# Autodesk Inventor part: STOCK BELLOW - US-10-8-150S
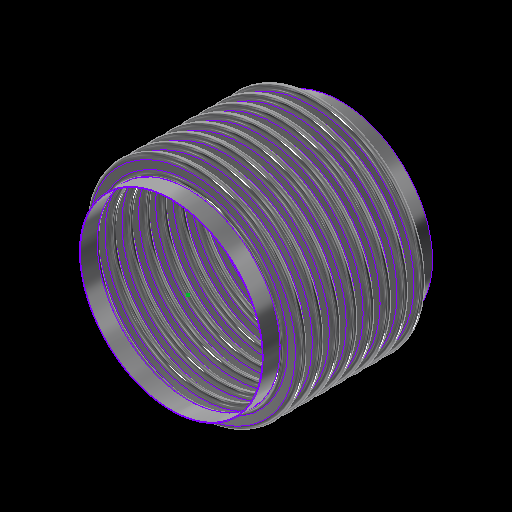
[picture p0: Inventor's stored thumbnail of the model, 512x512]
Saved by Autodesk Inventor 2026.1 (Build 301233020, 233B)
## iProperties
Category: 18 GA (0.048 THICK)
RuleStatus: InUse
Created: 2024-01
Part Number: STOCK BELLOW - US-10-8-150S
Project: =STOCK BELLOWS: <Stock Number><SFILL>
Material: ASTM A240-304
Description: =STOCK BELLOWS: <Stock Number>, <SID_> I.D., <SOD_> O.D., <SPLY_> PLY, <Category>, <SNET_CONS> CONS.<PITCH_><STANGENT_> TANGENT<SFILL>
Document SubType Name: Sheet Metal
Designer: GS
Stock Number: U.S-10-8-150S
Surface Area: 10368.5 cm^2
Volume: 628.223 cm^3
Sheet Metal Rule: Default
Appearance: STAINLESS STEEL
Mass: 5061.77 g
Density: 8.05729 g/cm^3
THK: 0.036
ID: 3.500
OD: 4.250
CONS_: 2
PITCH: 0.500
TANGENT: 0.500
BELLOWS_UPSET: 0.000
d79: 1.000
d82: 1.000
d83: 26.000
d84: 24.000
d174: 8
d214: 8
STHK_: 0.048
SID_: 10.750
SOD_: 12.750
SPITCH_: 1.000
STANGENT__: 1.000
SBELLOWS_UPSET_: 0.000
SDIFF_TAN: 1.000
d252: 2
d275: 2
d287: 0.050
d289: 0.500
d290: 0.000
SOD_NECK: 10 7/8
PLY: 1
PSET: 4.178
PBAR: 1.035
COUNTER: 1.500
NET_TUBE: 3.071
CONS: 2
S_CONS: 0
NET_CONS: 2
ID_M: 88.90 mm
OD_M: 107.95 mm
THK_M: 0.91 mm
ID_U: 3.500 in
OD_U: 4.250 in
THK_U: 0.036 in
TANGENT2: 0.500
TAN_TO_TAN: 1.000 in
d80: 2.571
d81: 10
SID: 2.375
SCONS_: 8
SPITCH: 0.250
STANGENT_: 1.000
SBELLOWS_UPSET: 0.000
SNET_CONS: 8
SS_CONS: 0
SCONS: 8
d190: 8
d191: 1
d192: 1
d193: 8
d194: 0
SIZE: 10.00
PRESSURE: 150
d230: 8
STANGENT: 4.000
SPLY_: 1
d233: 8
d234: 0
d263: 2
d265: 1
d268: 2
d269: 0
d286: 2
d288: 1
d291: 2
d292: 0
SREROLL: 0.750
BLETP: 0.000 ul
PRES_Copy: 85
MATTABLE: 20 GA (0.036 THICK)
PART_NUMBER: U.S-10-8-150S
PITCH_: =, <SPITCH_> PITCH,
CFILL: .
SFILL: .
MESH: ,
COMP: 1.48
EXT: 0.74
LAT: 0.33
ANG: 573
ASR: 2985
LSR: 8692
ANSR: 809
PRES: 150
COMPM: 14.8
EXTM: 7.4
LATM: 3.30
ASRM: 522.763
PRESM: 10.342
LSRM: 1522.230
ANSRM: 141.68
TEMPMIN: 20
TEMPMAX: 800
TEMPMINM: -7
TEMPMAXM: 427
WEIGHTM: 5.062
WEIGHT: 11.159
Author: GS
Keywords: 20 GA (0.036 THICK)
Comments: =STOCK BELLOW - <STOCK NUMBER>
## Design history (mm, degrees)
sketch "Sketch2"
  geometry: L1 (0, -177.245)-(0, 562.856) reference; L2 (45.364, 0)-(44.45, 0); L3 (48.082, -2.718)-(50.343, -2.718); L4 (48.082, -3.632)-(50.343, -3.632); L5 (50.343, -9.982)-(48.082, -9.982); L6 (50.343, -9.068)-(48.082, -9.068); L7 (45.364, -12.7)-(44.45, -12.7); L8 (48.082, 0)-(48.082, -12.7); L9 (50.343, -6.35)-(53.975, -6.35); L10 (44.45, 0)-(44.45, -12.7); L11 (20.376, 102.841)-(20.376, 101.926); L12 (58.262, 457.127)-(58.262, 349.177); L13 (58.262, 444.427)-(58.262, 336.477); L14 (93.133, -58.817)-(93.133, -71.517); L15 (118.746, -66.401)-(118.746, -66.401); L16 (50.343, -9.068)-(50.343, -9.982); L17 (48.082, -9.068)-(48.082, -9.982); L18 (48.082, -9.525)-(50.343, -9.525); L19 (53.975, 0)-(53.975, -12.7); L20 (-50.343, -9.068)-(-50.343, -9.982); L21 (-50.343, -2.718)-(-48.082, -2.718); L22 (-50.343, -3.632)-(-48.082, -3.632); L23 (-48.082, -9.068)-(-50.343, -9.068); L24 (-50.343, -9.525)-(-48.082, -9.525); L25 (-48.082, -9.982)-(-50.343, -9.982); L26 (-48.082, -9.068)-(-48.082, -9.982); L27 (-44.45, 0.653)-(-44.45, -12.047); L28 (-48.082, -6.35)-(-44.45, -6.35); L29 (-50.343, 0.653)-(-50.343, -12.7); L30 (-53.061, 0)-(-53.975, 0); L31 (-53.975, 0)-(-53.975, -12.7); L32 (-53.061, -12.7)-(-53.975, -12.7); A1 r 2.718 centre (48.082, 0) between (45.364, 0) and (48.082, -2.718); A2 r 3.632 centre (48.082, 0) between (44.45, 0) and (48.082, -3.632); A3 r 3.632 centre (50.343, -6.35) between (50.343, -9.982) and (50.343, -2.718); A4 r 2.718 centre (50.343, -6.35) between (50.343, -9.068) and (50.343, -3.632); A5 r 2.718 centre (48.082, -12.7) between (48.082, -9.982) and (45.364, -12.7); A6 r 3.632 centre (48.082, -12.7) between (48.082, -9.068) and (44.45, -12.7); A7 r 3.175 centre (50.343, -6.35) between (50.343, -9.525) and (53.518, -6.35); A8 r 3.175 centre (48.082, -12.7) between (48.082, -9.525) and (44.907, -12.7); A9 r 2.718 centre (-50.343, -12.7) between (-50.343, -9.982) and (-53.061, -12.7); A10 r 2.718 centre (-48.082, -6.35) between (-48.082, -9.068) and (-48.082, -3.632); A11 r 3.175 centre (-48.082, -6.35) between (-48.082, -9.525) and (-44.907, -6.35); A12 r 3.632 centre (-48.082, -6.35) between (-48.082, -9.982) and (-48.082, -2.718); A13 r 3.175 centre (-50.343, -12.7) between (-50.343, -9.525) and (-53.518, -12.7); A14 r 3.632 centre (-50.343, -12.7) between (-50.343, -9.068) and (-53.975, -12.7); A15 r 2.718 centre (-50.343, 0) between (-53.061, 0) and (-50.343, -2.718); A16 r 3.632 centre (-50.343, 0) between (-53.975, 0) and (-50.343, -3.632); 10 further points
  constraints: 62 end point, 38 point on circle, 20 tangent, 16 centre point, 12 parallel, 9 midpoint, 7 vertical, 6 coincident, 6 concentric, 6 point on line, 4 equal radius, 4 perpendicular, 3 horizontal, 1 collinear, 1 horizontal alignment, 10 other
  dimensions: "THK" = 0.9144 distance of L11.start L11.end; "ID" = 88.9 distance of L11.end point (20.376, 13.026); "OD" = 107.95 distance of L12.start L12.end; "PITCH" = 12.7 distance of L12.start L13.start; "TANGENT" = 12.7 distance of L14.start L14.end; "BELLOWS_UPSET" = 0 distance of L15.start L15.end; "d43" = 88.9 diameter of L10 L1 (= ID); "d44" = 107.95 diameter of L9.end L1 (= OD); "d45" = 0.9144 distance between parallel lines of L5 L6 (computed from THK, PLY); "d46" = 3.6322 radius of A3 (computed from PITCH, THK, PLY); "UPSET_PITCH" = 12.7 distance of L2.end L7.end (derived); "SIDEWALL_ANGLE" = 360 deg dimension on L3 L9 (derived); "CON_GAP" = 5.4356 distance of point (48.082, -9.068) point (48.082, -3.632) (derived); "TAN1" = 4.98728 dimension on A8 (derived); "TAN2" = 4.98728 dimension on A7 (derived); "LEG1" = 2.2606 distance of L18.start L18.end (derived); "d278" = 0.9144 distance between parallel lines of L25 L23 (derived); "d279" = 3.6322 radius of A12 (derived); "d280" = 12.7 distance of L30.end L31.end (derived); "d281" = 360 deg dimension on L21 L28 (derived); "d282" = 5.4356 distance of point (-50.343, -9.068) point (-50.343, -3.632) (derived); "d283" = 4.98728 dimension on A13 (derived); "d284" = 4.98728 dimension on A11 (derived); "d285" = 2.2606 distance of L24.start L24.end (derived); "d293" = 88.9 diameter of L27 L1 (derived); "d294" = 107.95 diameter of L31 L1 (derived)
  node "Sketch Rectangular Pattern1" dims "d31" = 25.4, "ID" = 88.9
  node "Sketch Rectangular Pattern2" dims "d39" = 25.4, "PITCH" = 12.7
revolve "CONS" stored, may be unused: angle "d48" = 90 deg
node "BELLOW MIDPLANE"
pattern_linear "Rectangular Pattern2" dims "d52" = 12.7 (= UPSET_PITCH)
sketch "Sketch5"
  geometry: C1 r 45.364 at (0, 0) reference; C2 r 44.45 at (0, 0) reference
extrude "TANGENT" new body sketch "Sketch5" distance "d53" = 12.7 (= TANGENT); taper "d54" = 0 deg
revolve "SAMETAN" stored, may be unused: angle "d65" = 90 deg
revolve "DIFFTAN" stored, may be unused: angle "d70" = 90 deg
sketch "Sketch9"
  geometry: L1 (53.319, 0)-(-53.319, 0) reference; L2 (0, -17.78)-(0, 17.78) reference; L3 (38.085, 0)-(-38.085, 0); L4 (38.085, -11.906)-(38.085, 11.906); L5 (25.385, -11.906)-(25.385, 11.906); L6 (13.15, 11.906)-(13.15, -11.906); L7 (-25.385, -11.906)-(-25.385, 11.906); L8 (-38.085, -11.906)-(-38.085, 11.906); L9 (37.291, -11.906)-(37.291, 11.906); L10 (38.085, -11.906)-(37.291, -11.906); L11 (38.085, 11.906)-(37.291, 11.906); L12 (13.546, 11.906)-(12.753, 11.906); L13 (12.753, 11.906)-(12.753, -11.906); L14 (12.753, -11.906)-(13.546, -11.906); L15 (13.546, -11.906)-(13.546, 11.906); L16 (-13.546, 11.906)-(-13.546, -11.906); L17 (-13.15, 11.906)-(-13.15, -11.906); L18 (-13.546, -11.906)-(-12.753, -11.906); L19 (-12.753, -11.906)-(-12.753, 11.906); L20 (-12.753, 11.906)-(-13.546, 11.906); L21 (-38.085, -11.906)-(-37.291, -11.906); L22 (-37.291, -11.906)-(-37.291, 11.906); L23 (-37.291, 11.906)-(-38.085, 11.906); L24 (-38.085, 11.906)-(-38.085, -11.906); L25 (38.085, -0.397)-(-38.085, -0.397); L26 (-38.085, -0.397)-(-38.085, 0.397); L27 (-38.085, 0.397)-(38.085, 0.397); L28 (38.085, 0.397)-(38.085, -0.397); L29 (-38.085, 11.906)-(38.085, 11.906); L30 (38.085, 11.906)-(38.085, 12.7); L31 (38.085, 12.7)-(-38.085, 12.7); L32 (-38.085, 12.7)-(-38.085, 11.906); L33 (38.085, -11.906)-(-38.085, -11.906); L34 (-38.085, -11.906)-(-38.085, -12.7); L35 (-38.085, -12.7)-(38.085, -12.7); L36 (38.085, -12.7)-(38.085, -11.906); 30 further points
  constraints: 68 end point, 13 midpoint, 13 parallel, 8 horizontal, 7 perpendicular, 6 equal length, 3 point on line, 2 vertical, 14 other
  dimensions: "d115" = 23.8125 distance of L4.start L4.end (derived); "d116" = 12.7 distance between parallel lines of L4 L5 (derived); "d117" = 12.23516 distance between parallel lines of L5 L6 (derived); "d125" = 38.53427 distance between parallel lines of L7 L6 (derived); "d127" = 12.7 distance between parallel lines of L8 L7 (derived); "d128" = 24.93516 distance between parallel lines of L6 L4 (derived); "d130" = 76.16943 distance between parallel lines of L8 L4 (derived); "RULER_THK" = 0.79375 distance between parallel lines of L4 L9; "d135" = 0.79375 distance of L13.end L14.end (derived); "d138" = 26.29911 distance of L13.end L16.end (derived); "d143" = 0.79375 distance of L22.end L8.end (derived); "d144" = 0.79375 distance between parallel lines of L27 L25 (derived)
extrude "RULER" join sketch "Sketch9" distance "d149" = 0.79375 (derived); taper "d150" = 0 deg
extrude "BARS" join sketch "Sketch9" distance "d151" = 0.79375 (derived); taper "d152" = 0 deg
pattern_linear "Rectangular Pattern4" dims "d155" = 26.29911 (derived)
sketch "Sketch13"
  geometry: L1 (93.149, -52.467)-(93.149, -77.867); L2 (137.744, 0)-(136.525, 0); L3 (137.744, -25.4)-(136.525, -25.4); L4 (154.965, -19.66)-(143.485, -19.66); L5 (154.965, -18.44)-(143.485, -18.44); L6 (154.965, -12.7)-(161.925, -12.7); L7 (143.485, -5.74)-(154.965, -5.74); L8 (143.485, 0)-(143.485, -25.4); L9 (136.525, 0)-(136.525, -25.4); L10 (58.254, -172.581)-(58.254, -496.431); L11 (58.254, -197.981)-(58.254, -521.831); L12 (58.254, -248.781)-(58.254, -572.631); L13 (58.254, -274.181)-(58.254, -598.031); L14 (58.254, -299.581)-(58.254, -623.431); L15 (58.254, -324.981)-(58.254, -648.831); L16 (58.254, -350.381)-(58.254, -674.231); L17 (58.254, -223.381)-(58.254, -547.231); L18 (20.376, 103.145)-(20.376, 101.926); L19 (143.485, -6.96)-(154.965, -6.96); L20 (0, -829.706)-(0, 258.621) reference; L21 (-32.385, 0)-(194.31, 0) reference; A1 r 5.74 centre (143.485, 0) between (137.744, 0) and (143.485, -5.74); A2 r 5.74 centre (143.485, -25.4) between (143.485, -19.66) and (137.744, -25.4); A3 r 6.96 centre (143.485, -25.4) between (143.485, -18.44) and (136.525, -25.4); A4 r 5.74 centre (154.965, -12.7) between (154.965, -18.44) and (154.965, -6.96); A5 r 6.96 centre (154.965, -12.7) between (154.965, -19.66) and (154.965, -5.74); A6 r 6.96 centre (143.485, 0) between (136.525, 0) and (143.485, -6.96); 6 further points; 1 other entity
  constraints: 38 end point, 15 point on circle, 9 tangent, 6 centre point, 6 parallel, 5 vertical alignment, 4 point on line, 4 vertical, 3 coincident, 3 concentric, 2 collinear, 2 equal radius, 1 horizontal, 1 perpendicular, 23 other
  dimensions: "SBELLOWS_UPSET_" = 0 distance of point (118.762, -66.401) point (118.762, -66.401); "STOTAL_THK_BELLOW__" = 1.2192 distance between parallel lines of L4 L5 (derived); "d224" = 6.9596 radius of A5 (derived); "d225" = 25.4 distance of L2.end L3.end (derived); "SSIDEWALL_ANGLE_" = 360 deg dimension on L7 L6 (derived); "SSCON_GAP_" = 11.4808 distance of point (143.485, -18.44) point (143.485, -6.96) (derived); "d235" = 273.05 diameter of L9 L20 (derived); "d236" = 323.85 diameter of L6.end L20 (derived)
  node "Sketch Rectangular Pattern4" dims "d228" = 25.4
  node "Sketch Rectangular Pattern5" dims "d229" = 25.4
revolve "SBELLOW" stored, may be unused: angle "d197" = 90 deg
pattern_linear "Rectangular Pattern5" dims "d204" = 25.4 (derived)
revolve "STANGENT" stored, may be unused: angle "d240" = 90 deg
revolve "SSAMETAN" stored, may be unused: angle "d241" = 90 deg
revolve "SDIFFTAN" stored, may be unused: angle "d246" = 90 deg
revolve "INVCON" stored, may be unused: angle "d295" = 90 deg
pattern_linear "Rectangular Pattern6" dims "d298" = 12.7 (derived)
revolve "INVTANGENT" stored, may be unused: angle "d302" = 90 deg
revolve "INVSAMETAN" stored, may be unused: angle "d307" = 90 deg
revolve "INVDIFFTAN" stored, may be unused: angle "d312" = 90 deg
sketch "ID BELLOW MOUNT CALC"
  geometry: L1 (44.45, 0)-(38.1, 0); L2 (38.1, 0)-(38.1, 12.7); L3 (38.1, 12.7)-(44.45, 12.7); L4 (44.45, 12.7)-(44.45, 0); L5 (36.513, 12.7)-(35.598, 12.7); L6 (35.598, 12.7)-(35.598, 0); L7 (35.598, 0)-(36.513, 0); L8 (36.513, 0)-(36.513, 12.7); L9 (0, -2.54)-(0, 15.24) reference; L10 (-8.89, 0)-(53.34, 0) reference; 1 further point
  constraints: 16 end point, 5 parallel, 2 collinear, 2 horizontal, 2 perpendicular
  dimensions: "d314" = 12.7 distance of L5.end L6.end (derived); "d315" = 0.9144 distance of L5.start L5.end (derived); "IG" = 1.5875 distance between parallel lines of L2 L8; "PIPE_OD" = 88.9 diameter of L4 L9; "PIPE_WALL" = 6.35 distance of L2.end L3.end; "ID_MT_BELLOW" = 71.1962 diameter of L6 L9 (derived)
revolve "CFILL" stored, may be unused: angle "d320" = 90 deg
pattern_linear "Rectangular Pattern7" dims "d323" = 12.7 (derived)
revolve "SFILL" stored, may be unused: angle "d324" = 90 deg
pattern_linear "Rectangular Pattern8" dims "d327" = 25.4 (derived)
node "STOCK BELLOW MIDPLANE"
node "BELLOW"
sketch "Sketch6"
  geometry: L1 (-12.7, 45.364)-(0, 45.364); L2 (0, 45.364)-(0, 44.45); L3 (0, 44.45)-(-12.7, 44.45); L4 (-12.7, 44.45)-(-12.7, 45.364); L5 (10.16, 0)-(-60.96, 0) reference; L6 (-38.1, -89.422)-(-38.1, 153.44) reference; 1 further point
  constraints: 8 end point, 2 parallel, 1 horizontal, 1 perpendicular
  dimensions: "d61" = 12.7 distance of L2.end L3.end (derived); "d62" = 0.9144 distance of L1.end L2.end (derived); "d63" = 88.9 diameter of L3 L5 (derived); "d64" = 25.4 distance between parallel lines of L4 L6 (derived)
sketch "Sketch12"
  geometry: 1 further point
sketch "Sketch14"
  geometry: L1 (-25.4, 137.744)-(0, 137.744); L2 (0, 137.744)-(0, 136.525); L3 (0, 136.525)-(-25.4, 136.525); L4 (-25.4, 136.525)-(-25.4, 137.744); L5 (5.08, 0)-(-30.48, 0) reference; L6 (0, -27.549)-(0, 165.293) reference; 1 further point
  constraints: 8 end point, 2 parallel, 1 collinear, 1 horizontal, 1 perpendicular
  dimensions: "d237" = 1.2192 distance of L3.end L1.start (derived); "d238" = 273.05 diameter of L3 L5 (derived); "d239" = 25.4 distance of L1.start L1.end (derived); "SOD_NECK" = 275.4884 diameter of L1 L5 (derived)
sketch "Sketch15"
  geometry: L1 (-27.549, 0)-(165.293, 0) reference; L2 (136.525, -203.2)-(137.744, -203.2); L3 (137.744, -203.2)-(137.744, -228.6); L4 (137.744, -228.6)-(136.525, -228.6); L5 (136.525, -228.6)-(136.525, -203.2); L6 (0, -276.86)-(0, 60.96) reference; 1 further point
  constraints: 8 end point, 2 parallel, 1 horizontal, 1 perpendicular
  dimensions: "d205" = 25.4 distance of L4.end L2.start (derived); "d206" = 1.2192 distance of L3.end L4.end (derived); "d207" = 273.05 diameter of L5 L6 (derived); "d208" = 203.2 distance between parallel lines of L1 L2 (derived)
node "TANGENT_"
node "SAME_TAN"
sketch "Sketch8"
  geometry: L1 (45.364, -25.4)-(44.45, -25.4); L2 (44.45, -25.4)-(44.45, -38.1); L3 (44.45, -38.1)-(45.364, -38.1); L4 (45.364, -38.1)-(45.364, -25.4); L5 (0, -48.26)-(0, 22.86) reference; L6 (-89.422, 0)-(153.44, 0) reference; 1 further point
  constraints: 8 end point, 2 parallel, 1 horizontal, 1 perpendicular
  dimensions: "d66" = 88.9 diameter of L2 L5 (derived); "TOTAL_THK_BELLOW" = 0.9144 distance of L2.end L3.end (derived); "d68" = 25.4 distance between parallel lines of L1 L6 (derived); "d69" = 12.7 distance of L1.end L2.end (derived)
node "DIFF_TAN"
node "Sketch Rectangular Pattern3" dims "d138" = 26.29911 (derived), "d141" = 25.4
node "SBELLOW_"
node "STANGENT_"
node "SSAME_TAN"
sketch "Sketch16"
  geometry: L1 (137.744, -203.2)-(136.525, -203.2); L2 (136.525, -203.2)-(136.525, -228.6); L3 (136.525, -228.6)-(137.744, -228.6); L4 (137.744, -228.6)-(137.744, -203.2); L5 (0, -276.86)-(0, 60.96) reference; L6 (-27.549, 0)-(165.293, 0) reference; 1 further point
  constraints: 8 end point, 2 parallel, 1 horizontal, 1 perpendicular
  dimensions: "SDIFF_TAN" = 25.4 distance of L3.end L1.start; "d243" = 1.2192 distance of L2.end L3.end (derived); "d244" = 203.2 distance between parallel lines of L1 L6 (derived); "d245" = 273.05 diameter of L2 L5 (derived)
node "SDIFF_TAN"
body "Solid15"
sketch "Sketch17"
  geometry: L1 (53.975, 12.7)-(53.061, 12.7); L2 (53.061, 12.7)-(53.061, 0); L3 (53.061, 0)-(53.975, 0); L4 (53.975, 0)-(53.975, 12.7); L5 (0, -2.54)-(0, 15.24) reference; L6 (-10.795, 0)-(64.77, 0) reference; 2 further points
  constraints: 8 end point, 2 parallel, 1 horizontal, 1 midpoint, 1 perpendicular, 1 point on line
  dimensions: "INVTANGENT" = 12.7 distance of L3.end L1.start (derived); "d300" = 0.9144 distance of L1.start L1.end (derived); "d301" = 107.95 diameter of L4 L5 (derived)
body "Solid16"
sketch "Sketch18"
  geometry: L1 (53.975, -25.4)-(53.061, -25.4); L2 (53.061, -25.4)-(53.061, -38.1); L3 (53.061, -38.1)-(53.975, -38.1); L4 (53.975, -38.1)-(53.975, -25.4); L5 (-10.795, 0)-(64.77, 0) reference; L6 (0, -48.26)-(0, 22.86) reference; 1 further point
  constraints: 8 end point, 2 parallel, 1 horizontal, 1 perpendicular
  dimensions: "d303" = 25.4 distance between parallel lines of L1 L5 (derived); "d304" = 12.7 distance of L3.end L1.start (derived); "d305" = 0.9144 distance of L2.end L3.end (derived); "d306" = 107.95 diameter of L4 L6 (derived)
body "Solid17"
sketch "Sketch19"
  geometry: L1 (53.975, -25.4)-(53.061, -25.4); L2 (53.061, -25.4)-(53.061, -38.1); L3 (53.061, -38.1)-(53.975, -38.1); L4 (53.975, -38.1)-(53.975, -25.4); L5 (0, -48.26)-(0, 22.86) reference; L6 (-10.795, 0)-(64.77, 0) reference; 1 further point
  constraints: 8 end point, 2 parallel, 1 horizontal, 1 perpendicular
  dimensions: "d308" = 12.7 distance of L1.end L2.end (derived); "d309" = 107.95 diameter of L4 L5 (derived); "d310" = 0.9144 distance of L2.end L3.end (derived); "d311" = 25.4 distance between parallel lines of L1 L6 (derived)
body "Solid18"
body "Solid19"
body "Solid20"
other parameters: "BMPL" = -101.6, "PSET" = 106.1212 (computed from OD, THK, PLY) [user parameter], "PBAR" = 26.29911 (= 0.570796 x PITCH + OD - ID) [user parameter; used in 1 equation term], "COUNTER" = 15 [user parameter], "NET_TUBE" = 77.99823 (computed from CONS_, PBAR, TANGENT) [user parameter], "S_CONS" = 0 [user parameter; used in 1 equation term], "ID_M" = 88.9 (= ID) [user parameter], "OD_M" = 107.95 (= OD) [user parameter], "THK_M" = 0.9144 (= THK) [user parameter], "ID_U" = 88.9 (= ID) [user parameter], "OD_U" = 107.95 (= OD) [user parameter], "THK_U" = 0.9144 (= THK) [user parameter], "D_UNITS" = 0 [user parameter], "TANGENT2" = 12.7 [user parameter], "TAN_TO_TAN" = 25.4 [user parameter], "OD_NECK" = 90.7288 [user parameter], "d79" = 25.4, "d80" = 65.29823 [user parameter], "d82" = 25.4, "d83" = 660.4, "d84" = 609.6, "sa_0" = 4, "FRAME_THK" = 0.79375 [user parameter], "CON_FLAT" = 12.23516 [user parameter], "SID" = 60.325 [user parameter], "SPITCH" = 6.35 [user parameter], "STANGENT_" = 25.4 [user parameter], "SBELLOWS_UPSET" = 0 [user parameter], "SS_CONS" = 0 [user parameter], "STAN_TO_TAN_" = 203.2 [user parameter], "d100" = 1.2192 [user parameter], "d191" = 25.4 [user parameter], "d194" = 0 [user parameter], "STANGENT" = 101.6 [user parameter], "d234" = 0 [user parameter], "SUPSET_PITCH_" = 25.4 [user parameter], "d269" = 0 [user parameter], "d287" = 1.27, "d289" = 12.7, "d290" = 0, "d292" = 0 [user parameter], "Thickness" = 3.048 (derived), "KFactor" = 4.4, "BendRadius" = 3.048 (derived), "BendReliefWidth" = 3.048 (derived), "BendReliefDepth" = 1.524 (derived), "CornerReliefSize" = 12.192 (derived), "SeamGap" = 0.00508, "MinimumRemnant" = 6.096 (derived), "TransitionRadius" = 3.048 (derived), "JacobiRadiusSize" = 3.048 (derived), "GapSize" = 3.048 (derived), "SREROLL" = 19.05 [user parameter], "CUR_STK_PITCH" = 25.4 [user parameter], "d328" = -101.6 (derived), "ASR" = 29850 [user parameter], "LSR" = 86920 [user parameter], "BLETP" = 0 [user parameter], "ASRM" = 5227.6305 [user parameter], "PRESM" = 103.41975 [user parameter], "LSRM" = 15222.2996 [user parameter], "ANSRM" = 1416.8017 [user parameter], "TEMPMIN" = 2664.83333 [user parameter], "TEMPMAX" = 6998.16667 [user parameter], "TEMPMINM" = 2664.83333 [user parameter], "TEMPMAXM" = 6998.16667 [user parameter], "WEIGHT" = 50.61771 [user parameter], "WEIGHTM" = 0.05062 [user parameter]
